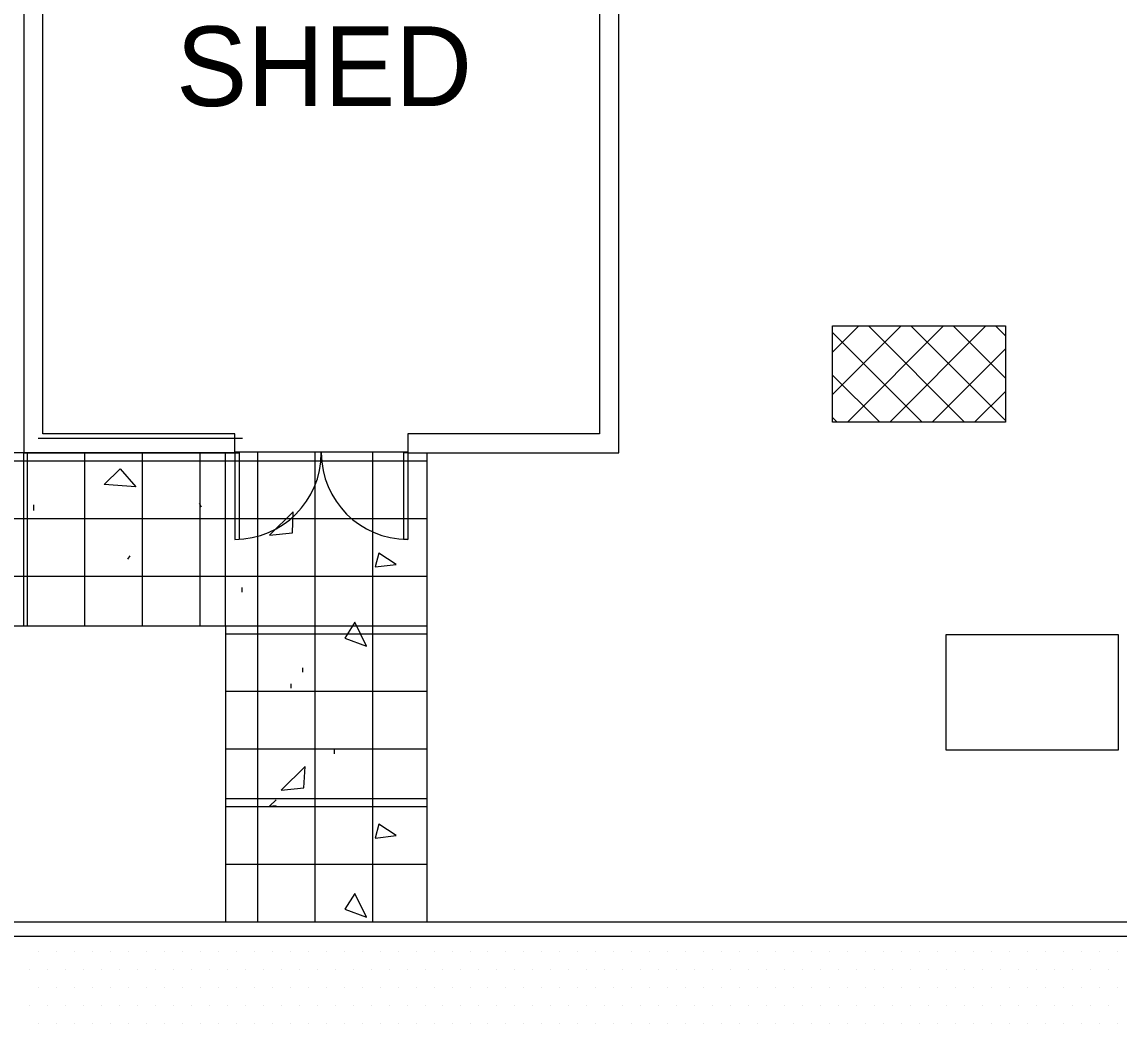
# Model space of a CAD drawing. Extents: x 6712138 to 6712574, y 1869536 to 1870160.
# Drawn here: x 6712318.4 to 6712356.5, y 1869836.28 to 1869871.04 of the extents above; entities that cross this region are included whole.
import ezdxf

# ---------------------------------------------------------------- set-up
doc = ezdxf.new("R2010")
doc.units = 0
for name, color, linetype in [('A-ANNO-TEXT', 7, 'Continuous'), ('A-DETL-GENF', 7, 'Continuous'), ('A-DETL-MBND', 7, 'Continuous'), ('A-FLOR-OTLN', 7, 'Continuous'), ('A-FLOR-PATT', 7, 'Continuous'), ('A-WALL-SHED', 7, 'Continuous'), ('G-DETL-LW01', 7, 'Continuous'), ('G-DETL-LW02', 7, 'Continuous'), ('L-SITE-PAVE', 7, 'Continuous')]:
    doc.layers.add(name, color=color, linetype=linetype)

msp = doc.modelspace()

# ---------------------------------------------------------------- linework, layer by layer
at = {"layer": 'A-DETL-GENF'}
for p, q in [((6712318.464, 1869882.073), (6712318.464, 1869856.073)), ((6712339.131, 1869856.073), (6712339.131, 1869882.073)), ((6712319.131, 1869856.739), (6712319.131, 1869881.406)), ((6712338.464, 1869881.406), (6712338.464, 1869856.739)), ((6712346.557, 1869859.577), (6712347.464, 1869860.483)), ((6712346.557, 1869858.103), (6712348.937, 1869860.483)), ((6712349.666, 1869857.143), (6712346.557, 1869860.251)), ((6712347.07, 1869857.143), (6712350.41, 1869860.483)), ((6712351.139, 1869857.143), (6712347.799, 1869860.483)), ((6712348.543, 1869857.143), (6712351.883, 1869860.483)), ((6712352.557, 1869857.198), (6712349.272, 1869860.483)), ((6712352.557, 1869858.671), (6712350.745, 1869860.483)), ((6712352.557, 1869860.144), (6712352.218, 1869860.483)), ((6712350.016, 1869857.143), (6712352.557, 1869859.684)), ((6712348.192, 1869857.143), (6712346.557, 1869858.778)), ((6712351.489, 1869857.143), (6712352.557, 1869858.211)), ((6712346.719, 1869857.143), (6712346.557, 1869857.305)), ((6712325.797, 1869856.739), (6712319.131, 1869856.739)), ((6712325.797, 1869856.739), (6712319.131, 1869856.739)), ((6712325.797, 1869856.073), (6712325.797, 1869856.739)), ((6712338.464, 1869856.739), (6712331.797, 1869856.739)), ((6712331.797, 1869856.739), (6712331.797, 1869856.073)), ((6712318.464, 1869856.073), (6712325.797, 1869856.073)), ((6712318.588, 1869850.073), (6712318.588, 1869856.073)), ((6712320.588, 1869850.073), (6712320.588, 1869856.073)), ((6712322.588, 1869850.073), (6712322.588, 1869856.073)), ((6712324.588, 1869850.073), (6712324.588, 1869856.073)), ((6712326.588, 1869839.781), (6712326.588, 1869856.073)), ((6712328.588, 1869839.781), (6712328.588, 1869856.073)), ((6712330.588, 1869839.781), (6712330.588, 1869856.073)), ((6712331.797, 1869856.073), (6712339.131, 1869856.073)), ((6712332.466, 1869855.788), (6712313.371, 1869855.788)), ((6712332.466, 1869853.788), (6712313.371, 1869853.788)), ((6712332.466, 1869851.788), (6712313.371, 1869851.788)), ((6712332.466, 1869849.788), (6712325.466, 1869849.788)), ((6712332.466, 1869847.788), (6712325.466, 1869847.788)), ((6712332.466, 1869845.788), (6712325.466, 1869845.788)), ((6712332.466, 1869843.788), (6712325.466, 1869843.788)), ((6712332.466, 1869841.788), (6712325.466, 1869841.788)), ((6712332.466, 1869839.788), (6712325.466, 1869839.788))]:
    msp.add_line(p, q, dxfattribs=at)
at = {"layer": 'A-DETL-MBND'}
for p, q in [((6712325.797, 1869856.073), (6712325.797, 1869853.073)), ((6712325.797, 1869856.073), (6712325.943, 1869856.073)), ((6712325.943, 1869856.073), (6712325.943, 1869853.076)), ((6712331.651, 1869856.073), (6712331.651, 1869853.073)), ((6712331.797, 1869856.073), (6712331.651, 1869856.073)), ((6712331.797, 1869856.073), (6712331.797, 1869853.073)), ((6712331.797, 1869853.073), (6712331.651, 1869853.073))]:
    msp.add_line(p, q, dxfattribs=at)
for centre, start, end in [((6712325.797, 1869856.073), 270, 0), ((6712331.797, 1869856.073), 180, 270)]:
    msp.add_arc(centre, 3, start, end, dxfattribs=at)
at = {"layer": 'A-FLOR-OTLN'}
for points in [[(6712251.183, 1869839.781), (6712251.183, 1869722.323), (6712419.14, 1869722.323), (6712419.14, 1869718.864), (6712468.641, 1869718.864), (6712468.641, 1869839.781)], [(6712251.683, 1869839.281), (6712251.683, 1869722.823), (6712419.64, 1869722.823), (6712419.64, 1869719.364), (6712468.141, 1869719.364), (6712468.141, 1869839.281)]]:
    msp.add_lwpolyline(points, close=True, dxfattribs=at)
at = {"layer": 'A-FLOR-PATT'}
for p, q in [((6712318.812, 1869854.076), (6712318.812, 1869854.276)), ((6712324.642, 1869854.196), (6712324.562, 1869854.316)), ((6712322.082, 1869852.386), (6712322.162, 1869852.506)), ((6712326.052, 1869851.246), (6712326.052, 1869851.406)), ((6712328.154, 1869848.465), (6712328.154, 1869848.615)), ((6712327.752, 1869847.906), (6712327.752, 1869848.056)), ((6712329.254, 1869845.625), (6712329.254, 1869845.775)), ((6712318.962, 1869838.782), (6712318.962, 1869838.782)), ((6712319.587, 1869838.782), (6712319.587, 1869838.782)), ((6712320.212, 1869838.782), (6712320.212, 1869838.782)), ((6712320.837, 1869838.782), (6712320.837, 1869838.782)), ((6712321.462, 1869838.782), (6712321.462, 1869838.782)), ((6712322.087, 1869838.782), (6712322.087, 1869838.782)), ((6712322.712, 1869838.782), (6712322.712, 1869838.782)), ((6712323.337, 1869838.782), (6712323.337, 1869838.782)), ((6712323.962, 1869838.782), (6712323.962, 1869838.782)), ((6712324.587, 1869838.782), (6712324.587, 1869838.782)), ((6712325.212, 1869838.782), (6712325.212, 1869838.782)), ((6712325.837, 1869838.782), (6712325.837, 1869838.782)), ((6712326.462, 1869838.782), (6712326.462, 1869838.782)), ((6712327.087, 1869838.782), (6712327.087, 1869838.782)), ((6712327.712, 1869838.782), (6712327.712, 1869838.782)), ((6712328.337, 1869838.782), (6712328.337, 1869838.782)), ((6712328.962, 1869838.782), (6712328.962, 1869838.782)), ((6712329.587, 1869838.782), (6712329.587, 1869838.782)), ((6712330.212, 1869838.782), (6712330.212, 1869838.782)), ((6712330.837, 1869838.782), (6712330.837, 1869838.782)), ((6712331.462, 1869838.782), (6712331.462, 1869838.782)), ((6712332.087, 1869838.782), (6712332.087, 1869838.782)), ((6712332.712, 1869838.782), (6712332.712, 1869838.782)), ((6712333.337, 1869838.782), (6712333.337, 1869838.782)), ((6712333.962, 1869838.782), (6712333.962, 1869838.782)), ((6712334.587, 1869838.782), (6712334.587, 1869838.782)), ((6712335.212, 1869838.782), (6712335.212, 1869838.782)), ((6712335.837, 1869838.782), (6712335.837, 1869838.782)), ((6712336.462, 1869838.782), (6712336.462, 1869838.782)), ((6712337.087, 1869838.782), (6712337.087, 1869838.782)), ((6712337.712, 1869838.782), (6712337.712, 1869838.782)), ((6712338.337, 1869838.782), (6712338.337, 1869838.782)), ((6712338.962, 1869838.782), (6712338.962, 1869838.782)), ((6712339.587, 1869838.782), (6712339.587, 1869838.782)), ((6712340.212, 1869838.782), (6712340.212, 1869838.782)), ((6712340.837, 1869838.782), (6712340.837, 1869838.782)), ((6712341.462, 1869838.782), (6712341.462, 1869838.782)), ((6712342.087, 1869838.782), (6712342.087, 1869838.782)), ((6712342.712, 1869838.782), (6712342.712, 1869838.782)), ((6712343.337, 1869838.782), (6712343.337, 1869838.782)), ((6712343.962, 1869838.782), (6712343.962, 1869838.782)), ((6712344.587, 1869838.782), (6712344.587, 1869838.782)), ((6712345.212, 1869838.782), (6712345.212, 1869838.782)), ((6712345.837, 1869838.782), (6712345.837, 1869838.782)), ((6712346.462, 1869838.782), (6712346.462, 1869838.782)), ((6712347.087, 1869838.782), (6712347.087, 1869838.782)), ((6712347.712, 1869838.782), (6712347.712, 1869838.782)), ((6712348.337, 1869838.782), (6712348.337, 1869838.782)), ((6712348.962, 1869838.782), (6712348.962, 1869838.782)), ((6712349.587, 1869838.782), (6712349.587, 1869838.782)), ((6712350.212, 1869838.782), (6712350.212, 1869838.782)), ((6712350.837, 1869838.782), (6712350.837, 1869838.782)), ((6712351.462, 1869838.782), (6712351.462, 1869838.782)), ((6712352.087, 1869838.782), (6712352.087, 1869838.782)), ((6712352.712, 1869838.782), (6712352.712, 1869838.782)), ((6712353.337, 1869838.782), (6712353.337, 1869838.782)), ((6712353.962, 1869838.782), (6712353.962, 1869838.782)), ((6712354.587, 1869838.782), (6712354.587, 1869838.782)), ((6712355.212, 1869838.782), (6712355.212, 1869838.782)), ((6712355.837, 1869838.782), (6712355.837, 1869838.782)), ((6712356.462, 1869838.782), (6712356.462, 1869838.782)), ((6712318.649, 1869838.157), (6712318.649, 1869838.157)), ((6712319.274, 1869838.157), (6712319.274, 1869838.157)), ((6712319.899, 1869838.157), (6712319.899, 1869838.157)), ((6712320.524, 1869838.157), (6712320.524, 1869838.157)), ((6712321.149, 1869838.157), (6712321.149, 1869838.157)), ((6712321.774, 1869838.157), (6712321.774, 1869838.157)), ((6712322.399, 1869838.157), (6712322.399, 1869838.157)), ((6712323.024, 1869838.157), (6712323.024, 1869838.157)), ((6712323.649, 1869838.157), (6712323.649, 1869838.157)), ((6712324.274, 1869838.157), (6712324.274, 1869838.157)), ((6712324.899, 1869838.157), (6712324.899, 1869838.157)), ((6712325.524, 1869838.157), (6712325.524, 1869838.157)), ((6712326.149, 1869838.157), (6712326.149, 1869838.157)), ((6712326.774, 1869838.157), (6712326.774, 1869838.157)), ((6712327.399, 1869838.157), (6712327.399, 1869838.157)), ((6712328.024, 1869838.157), (6712328.024, 1869838.157)), ((6712328.649, 1869838.157), (6712328.649, 1869838.157)), ((6712329.274, 1869838.157), (6712329.274, 1869838.157)), ((6712329.899, 1869838.157), (6712329.899, 1869838.157)), ((6712330.524, 1869838.157), (6712330.524, 1869838.157)), ((6712331.149, 1869838.157), (6712331.149, 1869838.157)), ((6712331.774, 1869838.157), (6712331.774, 1869838.157)), ((6712332.399, 1869838.157), (6712332.399, 1869838.157)), ((6712333.024, 1869838.157), (6712333.024, 1869838.157)), ((6712333.649, 1869838.157), (6712333.649, 1869838.157)), ((6712334.274, 1869838.157), (6712334.274, 1869838.157)), ((6712334.899, 1869838.157), (6712334.899, 1869838.157)), ((6712335.524, 1869838.157), (6712335.524, 1869838.157)), ((6712336.149, 1869838.157), (6712336.149, 1869838.157)), ((6712336.774, 1869838.157), (6712336.774, 1869838.157)), ((6712337.399, 1869838.157), (6712337.399, 1869838.157)), ((6712338.024, 1869838.157), (6712338.024, 1869838.157)), ((6712338.649, 1869838.157), (6712338.649, 1869838.157)), ((6712339.274, 1869838.157), (6712339.274, 1869838.157)), ((6712339.899, 1869838.157), (6712339.899, 1869838.157)), ((6712340.524, 1869838.157), (6712340.524, 1869838.157)), ((6712341.149, 1869838.157), (6712341.149, 1869838.157)), ((6712341.774, 1869838.157), (6712341.774, 1869838.157)), ((6712342.399, 1869838.157), (6712342.399, 1869838.157)), ((6712343.024, 1869838.157), (6712343.024, 1869838.157)), ((6712343.649, 1869838.157), (6712343.649, 1869838.157)), ((6712344.274, 1869838.157), (6712344.274, 1869838.157)), ((6712344.899, 1869838.157), (6712344.899, 1869838.157)), ((6712345.524, 1869838.157), (6712345.524, 1869838.157)), ((6712346.149, 1869838.157), (6712346.149, 1869838.157)), ((6712346.774, 1869838.157), (6712346.774, 1869838.157)), ((6712347.399, 1869838.157), (6712347.399, 1869838.157)), ((6712348.024, 1869838.157), (6712348.024, 1869838.157)), ((6712348.649, 1869838.157), (6712348.649, 1869838.157)), ((6712349.274, 1869838.157), (6712349.274, 1869838.157)), ((6712349.899, 1869838.157), (6712349.899, 1869838.157)), ((6712350.524, 1869838.157), (6712350.524, 1869838.157)), ((6712351.149, 1869838.157), (6712351.149, 1869838.157)), ((6712351.774, 1869838.157), (6712351.774, 1869838.157)), ((6712352.399, 1869838.157), (6712352.399, 1869838.157)), ((6712353.024, 1869838.157), (6712353.024, 1869838.157)), ((6712353.649, 1869838.157), (6712353.649, 1869838.157)), ((6712354.274, 1869838.157), (6712354.274, 1869838.157)), ((6712354.899, 1869838.157), (6712354.899, 1869838.157)), ((6712355.524, 1869838.157), (6712355.524, 1869838.157)), ((6712356.149, 1869838.157), (6712356.149, 1869838.157)), ((6712318.962, 1869837.532), (6712318.962, 1869837.532)), ((6712319.587, 1869837.532), (6712319.587, 1869837.532)), ((6712320.212, 1869837.532), (6712320.212, 1869837.532)), ((6712320.837, 1869837.532), (6712320.837, 1869837.532)), ((6712321.462, 1869837.532), (6712321.462, 1869837.532)), ((6712322.087, 1869837.532), (6712322.087, 1869837.532)), ((6712322.712, 1869837.532), (6712322.712, 1869837.532)), ((6712323.337, 1869837.532), (6712323.337, 1869837.532)), ((6712323.962, 1869837.532), (6712323.962, 1869837.532)), ((6712324.587, 1869837.532), (6712324.587, 1869837.532)), ((6712325.212, 1869837.532), (6712325.212, 1869837.532)), ((6712325.837, 1869837.532), (6712325.837, 1869837.532)), ((6712326.462, 1869837.532), (6712326.462, 1869837.532)), ((6712327.087, 1869837.532), (6712327.087, 1869837.532)), ((6712327.712, 1869837.532), (6712327.712, 1869837.532)), ((6712328.337, 1869837.532), (6712328.337, 1869837.532)), ((6712328.962, 1869837.532), (6712328.962, 1869837.532)), ((6712329.587, 1869837.532), (6712329.587, 1869837.532)), ((6712330.212, 1869837.532), (6712330.212, 1869837.532)), ((6712330.837, 1869837.532), (6712330.837, 1869837.532)), ((6712331.462, 1869837.532), (6712331.462, 1869837.532)), ((6712332.087, 1869837.532), (6712332.087, 1869837.532)), ((6712332.712, 1869837.532), (6712332.712, 1869837.532)), ((6712333.337, 1869837.532), (6712333.337, 1869837.532)), ((6712333.962, 1869837.532), (6712333.962, 1869837.532)), ((6712334.587, 1869837.532), (6712334.587, 1869837.532)), ((6712335.212, 1869837.532), (6712335.212, 1869837.532)), ((6712335.837, 1869837.532), (6712335.837, 1869837.532)), ((6712336.462, 1869837.532), (6712336.462, 1869837.532)), ((6712337.087, 1869837.532), (6712337.087, 1869837.532)), ((6712337.712, 1869837.532), (6712337.712, 1869837.532)), ((6712338.337, 1869837.532), (6712338.337, 1869837.532)), ((6712338.962, 1869837.532), (6712338.962, 1869837.532)), ((6712339.587, 1869837.532), (6712339.587, 1869837.532)), ((6712340.212, 1869837.532), (6712340.212, 1869837.532)), ((6712340.837, 1869837.532), (6712340.837, 1869837.532)), ((6712341.462, 1869837.532), (6712341.462, 1869837.532)), ((6712342.087, 1869837.532), (6712342.087, 1869837.532)), ((6712342.712, 1869837.532), (6712342.712, 1869837.532)), ((6712343.337, 1869837.532), (6712343.337, 1869837.532)), ((6712343.962, 1869837.532), (6712343.962, 1869837.532)), ((6712344.587, 1869837.532), (6712344.587, 1869837.532)), ((6712345.212, 1869837.532), (6712345.212, 1869837.532)), ((6712345.837, 1869837.532), (6712345.837, 1869837.532)), ((6712346.462, 1869837.532), (6712346.462, 1869837.532)), ((6712347.087, 1869837.532), (6712347.087, 1869837.532)), ((6712347.712, 1869837.532), (6712347.712, 1869837.532)), ((6712348.337, 1869837.532), (6712348.337, 1869837.532)), ((6712348.962, 1869837.532), (6712348.962, 1869837.532)), ((6712349.587, 1869837.532), (6712349.587, 1869837.532)), ((6712350.212, 1869837.532), (6712350.212, 1869837.532)), ((6712350.837, 1869837.532), (6712350.837, 1869837.532)), ((6712351.462, 1869837.532), (6712351.462, 1869837.532)), ((6712352.087, 1869837.532), (6712352.087, 1869837.532)), ((6712352.712, 1869837.532), (6712352.712, 1869837.532)), ((6712353.337, 1869837.532), (6712353.337, 1869837.532)), ((6712353.962, 1869837.532), (6712353.962, 1869837.532)), ((6712354.587, 1869837.532), (6712354.587, 1869837.532)), ((6712355.212, 1869837.532), (6712355.212, 1869837.532)), ((6712355.837, 1869837.532), (6712355.837, 1869837.532)), ((6712356.462, 1869837.532), (6712356.462, 1869837.532)), ((6712318.649, 1869836.907), (6712318.649, 1869836.907)), ((6712319.274, 1869836.907), (6712319.274, 1869836.907)), ((6712319.899, 1869836.907), (6712319.899, 1869836.907)), ((6712320.524, 1869836.907), (6712320.524, 1869836.907)), ((6712321.149, 1869836.907), (6712321.149, 1869836.907)), ((6712321.774, 1869836.907), (6712321.774, 1869836.907)), ((6712322.399, 1869836.907), (6712322.399, 1869836.907)), ((6712323.024, 1869836.907), (6712323.024, 1869836.907)), ((6712323.649, 1869836.907), (6712323.649, 1869836.907)), ((6712324.274, 1869836.907), (6712324.274, 1869836.907)), ((6712324.899, 1869836.907), (6712324.899, 1869836.907)), ((6712325.524, 1869836.907), (6712325.524, 1869836.907)), ((6712326.149, 1869836.907), (6712326.149, 1869836.907)), ((6712326.774, 1869836.907), (6712326.774, 1869836.907)), ((6712327.399, 1869836.907), (6712327.399, 1869836.907)), ((6712328.024, 1869836.907), (6712328.024, 1869836.907)), ((6712328.649, 1869836.907), (6712328.649, 1869836.907)), ((6712329.274, 1869836.907), (6712329.274, 1869836.907)), ((6712329.899, 1869836.907), (6712329.899, 1869836.907)), ((6712330.524, 1869836.907), (6712330.524, 1869836.907)), ((6712331.149, 1869836.907), (6712331.149, 1869836.907)), ((6712331.774, 1869836.907), (6712331.774, 1869836.907)), ((6712332.399, 1869836.907), (6712332.399, 1869836.907)), ((6712333.024, 1869836.907), (6712333.024, 1869836.907)), ((6712333.649, 1869836.907), (6712333.649, 1869836.907)), ((6712334.274, 1869836.907), (6712334.274, 1869836.907)), ((6712334.899, 1869836.907), (6712334.899, 1869836.907)), ((6712335.524, 1869836.907), (6712335.524, 1869836.907)), ((6712336.149, 1869836.907), (6712336.149, 1869836.907)), ((6712336.774, 1869836.907), (6712336.774, 1869836.907)), ((6712337.399, 1869836.907), (6712337.399, 1869836.907)), ((6712338.024, 1869836.907), (6712338.024, 1869836.907)), ((6712338.649, 1869836.907), (6712338.649, 1869836.907)), ((6712339.274, 1869836.907), (6712339.274, 1869836.907)), ((6712339.899, 1869836.907), (6712339.899, 1869836.907)), ((6712340.524, 1869836.907), (6712340.524, 1869836.907)), ((6712341.149, 1869836.907), (6712341.149, 1869836.907)), ((6712341.774, 1869836.907), (6712341.774, 1869836.907)), ((6712342.399, 1869836.907), (6712342.399, 1869836.907)), ((6712343.024, 1869836.907), (6712343.024, 1869836.907)), ((6712343.649, 1869836.907), (6712343.649, 1869836.907)), ((6712344.274, 1869836.907), (6712344.274, 1869836.907)), ((6712344.899, 1869836.907), (6712344.899, 1869836.907)), ((6712345.524, 1869836.907), (6712345.524, 1869836.907)), ((6712346.149, 1869836.907), (6712346.149, 1869836.907)), ((6712346.774, 1869836.907), (6712346.774, 1869836.907)), ((6712347.399, 1869836.907), (6712347.399, 1869836.907)), ((6712348.024, 1869836.907), (6712348.024, 1869836.907)), ((6712348.649, 1869836.907), (6712348.649, 1869836.907)), ((6712349.274, 1869836.907), (6712349.274, 1869836.907)), ((6712349.899, 1869836.907), (6712349.899, 1869836.907)), ((6712350.524, 1869836.907), (6712350.524, 1869836.907)), ((6712351.149, 1869836.907), (6712351.149, 1869836.907)), ((6712351.774, 1869836.907), (6712351.774, 1869836.907)), ((6712352.399, 1869836.907), (6712352.399, 1869836.907)), ((6712353.024, 1869836.907), (6712353.024, 1869836.907)), ((6712353.649, 1869836.907), (6712353.649, 1869836.907)), ((6712354.274, 1869836.907), (6712354.274, 1869836.907)), ((6712354.899, 1869836.907), (6712354.899, 1869836.907)), ((6712355.524, 1869836.907), (6712355.524, 1869836.907)), ((6712356.149, 1869836.907), (6712356.149, 1869836.907)), ((6712318.962, 1869836.282), (6712318.962, 1869836.282)), ((6712319.587, 1869836.282), (6712319.587, 1869836.282)), ((6712320.212, 1869836.282), (6712320.212, 1869836.282)), ((6712320.837, 1869836.282), (6712320.837, 1869836.282)), ((6712321.462, 1869836.282), (6712321.462, 1869836.282)), ((6712322.087, 1869836.282), (6712322.087, 1869836.282)), ((6712322.712, 1869836.282), (6712322.712, 1869836.282)), ((6712323.337, 1869836.282), (6712323.337, 1869836.282)), ((6712323.962, 1869836.282), (6712323.962, 1869836.282)), ((6712324.587, 1869836.282), (6712324.587, 1869836.282)), ((6712325.212, 1869836.282), (6712325.212, 1869836.282)), ((6712325.837, 1869836.282), (6712325.837, 1869836.282)), ((6712326.462, 1869836.282), (6712326.462, 1869836.282)), ((6712327.087, 1869836.282), (6712327.087, 1869836.282)), ((6712327.712, 1869836.282), (6712327.712, 1869836.282)), ((6712328.337, 1869836.282), (6712328.337, 1869836.282)), ((6712328.962, 1869836.282), (6712328.962, 1869836.282)), ((6712329.587, 1869836.282), (6712329.587, 1869836.282)), ((6712330.212, 1869836.282), (6712330.212, 1869836.282)), ((6712330.837, 1869836.282), (6712330.837, 1869836.282)), ((6712331.462, 1869836.282), (6712331.462, 1869836.282)), ((6712332.087, 1869836.282), (6712332.087, 1869836.282)), ((6712332.712, 1869836.282), (6712332.712, 1869836.282)), ((6712333.337, 1869836.282), (6712333.337, 1869836.282)), ((6712333.962, 1869836.282), (6712333.962, 1869836.282)), ((6712334.587, 1869836.282), (6712334.587, 1869836.282)), ((6712335.212, 1869836.282), (6712335.212, 1869836.282)), ((6712335.837, 1869836.282), (6712335.837, 1869836.282)), ((6712336.462, 1869836.282), (6712336.462, 1869836.282)), ((6712337.087, 1869836.282), (6712337.087, 1869836.282)), ((6712337.712, 1869836.282), (6712337.712, 1869836.282)), ((6712338.337, 1869836.282), (6712338.337, 1869836.282)), ((6712338.962, 1869836.282), (6712338.962, 1869836.282)), ((6712339.587, 1869836.282), (6712339.587, 1869836.282)), ((6712340.212, 1869836.282), (6712340.212, 1869836.282)), ((6712340.837, 1869836.282), (6712340.837, 1869836.282)), ((6712341.462, 1869836.282), (6712341.462, 1869836.282)), ((6712342.087, 1869836.282), (6712342.087, 1869836.282)), ((6712342.712, 1869836.282), (6712342.712, 1869836.282)), ((6712343.337, 1869836.282), (6712343.337, 1869836.282)), ((6712343.962, 1869836.282), (6712343.962, 1869836.282)), ((6712344.587, 1869836.282), (6712344.587, 1869836.282)), ((6712345.212, 1869836.282), (6712345.212, 1869836.282)), ((6712345.837, 1869836.282), (6712345.837, 1869836.282)), ((6712346.462, 1869836.282), (6712346.462, 1869836.282)), ((6712347.087, 1869836.282), (6712347.087, 1869836.282)), ((6712347.712, 1869836.282), (6712347.712, 1869836.282)), ((6712348.337, 1869836.282), (6712348.337, 1869836.282)), ((6712348.962, 1869836.282), (6712348.962, 1869836.282)), ((6712349.587, 1869836.282), (6712349.587, 1869836.282)), ((6712350.212, 1869836.282), (6712350.212, 1869836.282)), ((6712350.837, 1869836.282), (6712350.837, 1869836.282)), ((6712351.462, 1869836.282), (6712351.462, 1869836.282)), ((6712352.087, 1869836.282), (6712352.087, 1869836.282)), ((6712352.712, 1869836.282), (6712352.712, 1869836.282)), ((6712353.337, 1869836.282), (6712353.337, 1869836.282)), ((6712353.962, 1869836.282), (6712353.962, 1869836.282)), ((6712354.587, 1869836.282), (6712354.587, 1869836.282)), ((6712355.212, 1869836.282), (6712355.212, 1869836.282)), ((6712355.837, 1869836.282), (6712355.837, 1869836.282)), ((6712356.462, 1869836.282), (6712356.462, 1869836.282))]:
    msp.add_line(p, q, dxfattribs=at)
for points in [[(6712321.252, 1869854.978), (6712321.812, 1869855.528), (6712322.352, 1869854.898)], [(6712327.792, 1869853.296), (6712327.822, 1869854.036), (6712327.002, 1869853.216)], [(6712330.674, 1869852.115), (6712331.394, 1869852.205), (6712330.794, 1869852.595)], [(6712329.614, 1869849.645), (6712330.364, 1869849.365), (6712329.964, 1869850.195)], [(6712328.194, 1869844.445), (6712328.234, 1869845.185), (6712327.404, 1869844.365)], [(6712330.674, 1869842.705), (6712331.394, 1869842.795), (6712330.794, 1869843.185)], [(6712329.614, 1869840.235), (6712330.364, 1869839.955), (6712329.964, 1869840.785)]]:
    msp.add_lwpolyline(points, close=True, dxfattribs=at)
msp.add_lwpolyline([(6712327.233, 1869844.037), (6712327.002, 1869843.806), (6712327.233, 1869843.829)], dxfattribs=at)
at = {"layer": 'A-WALL-SHED'}
msp.add_line((6712326.057, 1869856.573), (6712318.964, 1869856.573), dxfattribs=at)
at = {"layer": 'G-DETL-LW01'}
for p, q in [((6712325.797, 1869856.073), (6712313.371, 1869856.073)), ((6712331.797, 1869856.107), (6712325.797, 1869856.107)), ((6712332.466, 1869856.073), (6712332.466, 1869839.781)), ((6712313.371, 1869850.073), (6712325.466, 1869850.073)), ((6712325.466, 1869850.073), (6712325.466, 1869839.781))]:
    msp.add_line(p, q, dxfattribs=at)
at = {"layer": 'G-DETL-LW02'}
for points in [[(6712346.557, 1869860.483), (6712352.557, 1869860.483), (6712352.557, 1869857.143), (6712346.557, 1869857.143)], [(6712350.483, 1869845.763), (6712356.483, 1869845.763), (6712356.483, 1869849.763), (6712350.483, 1869849.763)]]:
    msp.add_lwpolyline(points, close=True, dxfattribs=at)
at = {"layer": 'L-SITE-PAVE'}
for p, q in [((6712318.466, 1869850.073), (6712318.466, 1869856.073)), ((6712325.466, 1869850.073), (6712325.466, 1869856.073)), ((6712325.466, 1869850.073), (6712332.466, 1869850.073)), ((6712325.466, 1869844.073), (6712332.466, 1869844.073))]:
    msp.add_line(p, q, dxfattribs=at)

# ---------------------------------------------------------------- texts
at = {"layer": 'A-ANNO-TEXT'}
msp.add_text('SHED', height=2.7662, dxfattribs=at).set_placement((6712323.756, 1869868.119))
msp.add_text('SHED', height=2.7662, dxfattribs=at).set_placement((6712323.756, 1869868.119))

doc.saveas('drawing.dxf')
